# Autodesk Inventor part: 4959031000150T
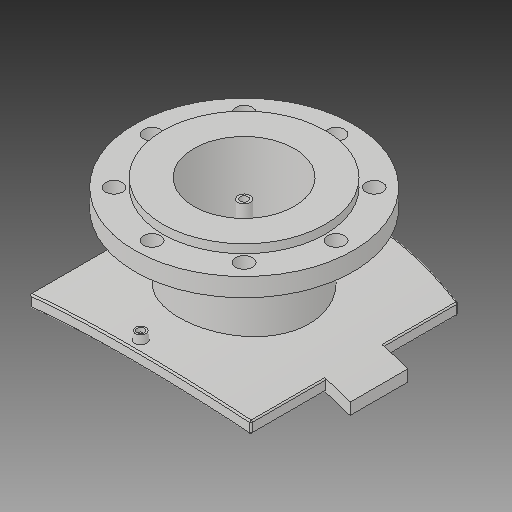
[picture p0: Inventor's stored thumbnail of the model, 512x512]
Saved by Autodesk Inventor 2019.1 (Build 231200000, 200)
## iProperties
Created: 2017-10
Part Number: 4959031000150T
Material: Generic
Description: PLASSON FLANGED BRANCH SADDLE 1000x150
Document SubType Name: Modeling
Designer: KIM
Mass: 2339.99 g
Surface Area: 3251.55 cm^2
Volume: 2339.99 cm^3
Density: 1 g/cm^3
Appearance: Default
Author: KIM
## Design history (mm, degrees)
derived "495904_495903.ipt"
feature "Solid1::495904_495903.ipt"
feature "Solid2::495904_495903.ipt"
tag "TaggingFeature1"
body "Solid1"
other parameters: "d1" = 15, "d2" = 288, "d4" = 0, "d6" = 75, "d7" = 0, "d12" = 525.6, "d13" = 14, "d14" = 135, "d16" = 5 deg, "d18" = 4, "d19" = 14, "d20" = 0, "d21" = 3, "d22" = 0, "d23" = 646, "d36" = 135, "d38" = 0, "d39" = 2, "d41" = 131, "d42" = 212, "d43" = 285, "d44" = 104.8, "d46" = 169.6, "d47" = 16, "d48" = 10.4, "d49" = 91.7, "d53" = 0, "d54" = 22, "d57" = 0, "d59" = 360 deg, "d61" = 24, "d63" = 0, "d66" = 131, "d67" = 15, "d68" = 65.5, "d70" = 0, "d71" = 2, "d_1" = 212, "H_" = 131, "x_" = 15, "D_" = 16, "DN_" = 131, "D_1" = 285, "t_" = 24, "s_" = 22
